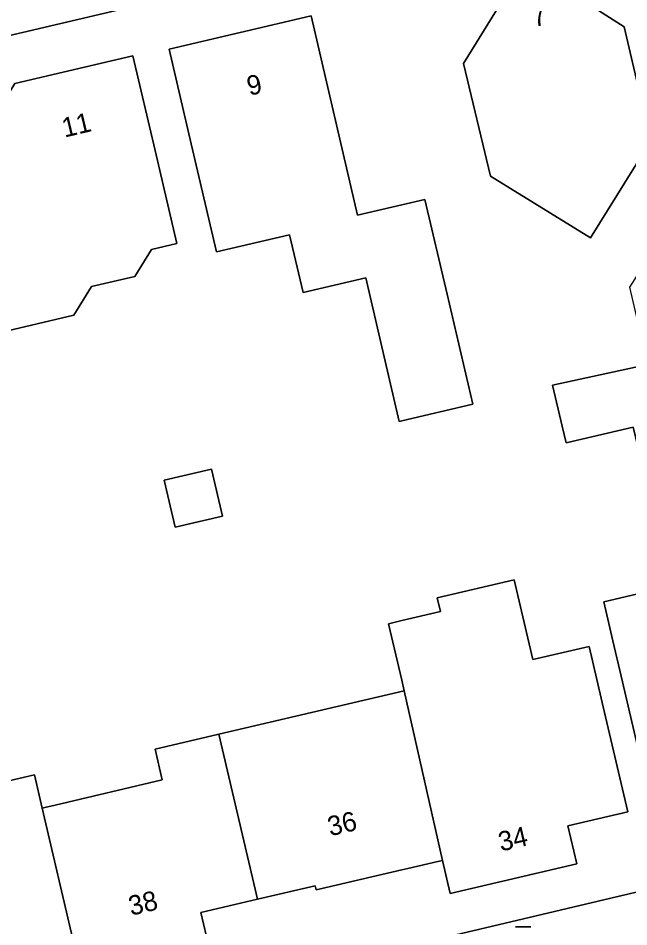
# Model space of a CAD drawing. Extents: x 158031 to 159244, y 380104 to 381214.
# Drawn here: x 158480.31 to 158511.66, y 380624.23 to 380670.9 of the extents above; entities that cross this region are included whole.
import ezdxf

# ---------------------------------------------------------------- set-up
doc = ezdxf.new("R2010")
doc.units = 0
for name, color, linetype in [('IMGEO_Erf', 7, 'Continuous'), ('IMGEO_Lichtmast', 7, 'Continuous'), ('IMGEO_Pand', 7, 'Continuous'), ('IMGEO_Pand_nummerreeks', 7, 'Continuous'), ('IMGEO_Voetpad_open', 7, 'Continuous')]:
    doc.layers.add(name, color=color, linetype=linetype)

msp = doc.modelspace()

# ---------------------------------------------------------------- linework, layer by layer
at = {"layer": 'IMGEO_Erf'}
for points in [[(158526.735, 380681.036), (158440.512, 380660.757), (158440.604, 380660.368), (158425.659, 380656.851), (158426.088, 380655.101), (158440.982, 380658.644), (158442.407, 380652.573), (158443.97, 380652.93), (158444.925, 380648.956), (158421.153, 380643.314), (158420.386, 380646.452), (158423.834, 380652.004), (158425.7, 380655.009), (158425.174, 380657.148), (158423.526, 380656.735)], [(158416.927, 380647.515), (158417.504, 380641.99), (158418.723, 380630.324), (158421.355, 380604.556), (158438.087, 380608.511), (158441.26, 380609.261), (158446.214, 380610.431), (158513.92, 380626.456), (158514.182, 380625.412), (158521.646, 380627.199), (158530.026, 380629.187), (158531.071, 380629.424), (158528.987, 380638.268), (158523.271, 380636.922), (158522.125, 380641.789), (158521.882, 380642.821), (158531.246, 380645.027), (158530.288, 380649.096), (158532.217, 380649.55), (158530.844, 380655.379)], [(158471.711, 380629.82), (158481.149, 380632.043), (158481.55, 380630.323), (158481.676, 380630.353), (158482.212, 380630.479), (158487.709, 380631.775), (158487.337, 380633.36), (158490.618, 380634.129), (158500.128, 380636.359), (158500, 380636.906), (158499.323, 380639.797), (158500, 380639.956), (158501.99, 380640.422), (158501.825, 380641.122), (158505.768, 380642.046), (158506.726, 380637.955), (158509.617, 380638.634), (158510.467, 380635.01), (158511.608, 380630.142), (158508.537, 380629.422), (158508.995, 380627.467), (158502.483, 380625.94), (158502.098, 380627.643), (158501.859, 380627.587), (158500.31, 380627.224), (158500, 380627.151), (158495.615, 380626.122), (158495.564, 380626.341), (158492.594, 380625.648), (158489.693, 380624.971), (158490.121, 380623.153)]]:
    msp.add_lwpolyline(points, dxfattribs=at)
for points in [[(158503.179, 380668.573), (158506.346, 380673.706), (158511.418, 380670.444), (158512.789, 380664.596), (158509.692, 380659.611), (158504.565, 380662.782)], [(158498.156, 380657.558), (158494.937, 380656.807), (158494.246, 380659.768), (158490.495, 380658.892), (158489.2, 380664.444), (158488.064, 380669.313), (158495.347, 380671.012), (158497.735, 380660.777), (158500, 380661.306), (158501.196, 380661.585), (158502.332, 380656.716), (158503.649, 380651.073), (158500, 380650.219), (158499.875, 380650.189)], [(158473.343, 380653.334), (158471.927, 380654.21), (158469.562, 380653.653), (158468.173, 380654.513), (158466.872, 380654.207), (158465.768, 380658.899), (158464.622, 380663.765), (158470.521, 380665.154), (158472.028, 380664.222), (158472.277, 380663.166), (158473.589, 380662.261), (158476.135, 380662.86), (158478.682, 380663.46), (158479.462, 380664.722), (158479.171, 380665.96), (158480.148, 380667.54), (158486.194, 380668.963), (158487.339, 380664.096), (158488.462, 380659.326), (158487.148, 380659.017), (158486.294, 380657.636), (158484.078, 380657.115), (158483.17, 380655.648), (158478.152, 380654.466)], [(158507.75, 380652.048), (158512.639, 380653.118), (158511.712, 380657.077), (158513.677, 380660.162), (158515.187, 380653.714), (158515.661, 380651.688), (158517.589, 380643.452), (158520.066, 380644.032), (158520.988, 380640.095), (158518.511, 380639.515), (158520.419, 380631.368), (158518.198, 380630.848), (158516.816, 380630.524), (158517.089, 380629.355), (158513.291, 380628.465), (158511.268, 380637.103), (158510.842, 380638.922), (158510.374, 380640.922), (158513.802, 380641.725), (158512.355, 380647.904), (158511.89, 380649.889), (158508.444, 380649.082), (158508.241, 380649.95)], [(158490.23, 380647.743), (158490.797, 380645.321), (158488.375, 380644.754), (158487.808, 380647.176)]]:
    msp.add_lwpolyline(points, close=True, dxfattribs=at)
at = {"layer": 'IMGEO_Lichtmast'}
for p, q in [((158505.845, 380624.231), (158506.635, 380624.231)), ((158506.635, 380624.231), (158505.845, 380624.231))]:
    msp.add_line(p, q, dxfattribs=at)
at = {"layer": 'IMGEO_Pand'}
for points in [[(158512.789, 380664.596), (158511.418, 380670.444), (158506.346, 380673.706), (158503.179, 380668.573), (158504.565, 380662.782), (158509.692, 380659.611)], [(158502.332, 380656.716), (158501.196, 380661.585), (158500, 380661.306), (158497.735, 380660.777), (158495.347, 380671.012), (158488.064, 380669.313), (158489.2, 380664.444), (158490.495, 380658.892), (158494.246, 380659.768), (158494.937, 380656.807), (158498.156, 380657.558), (158499.875, 380650.189), (158500, 380650.219), (158503.649, 380651.073)], [(158478.152, 380654.466), (158483.17, 380655.648), (158484.078, 380657.115), (158486.294, 380657.636), (158487.148, 380659.017), (158488.462, 380659.326), (158487.339, 380664.096), (158486.194, 380668.963), (158480.148, 380667.54), (158479.171, 380665.96), (158479.462, 380664.722), (158478.682, 380663.46), (158476.135, 380662.86)], [(158515.187, 380653.714), (158512.639, 380653.118), (158507.75, 380652.048), (158508.241, 380649.95), (158508.444, 380649.082), (158511.89, 380649.889), (158512.355, 380647.904), (158513.802, 380641.725), (158510.374, 380640.922), (158510.842, 380638.922), (158511.268, 380637.103), (158513.291, 380628.465), (158517.089, 380629.355), (158516.816, 380630.524), (158518.198, 380630.848), (158520.419, 380631.368), (158518.511, 380639.515), (158517.589, 380643.452), (158515.661, 380651.688)], [(158487.808, 380647.176), (158488.375, 380644.754), (158490.797, 380645.321), (158490.23, 380647.743)], [(158510.467, 380635.01), (158509.617, 380638.634), (158506.726, 380637.955), (158505.768, 380642.046), (158501.825, 380641.122), (158501.99, 380640.422), (158500, 380639.956), (158499.323, 380639.797), (158500, 380636.906), (158500.128, 380636.359), (158502.098, 380627.643), (158502.483, 380625.94), (158508.995, 380627.467), (158508.537, 380629.422), (158511.608, 380630.142)], [(158500.128, 380636.359), (158490.618, 380634.129), (158492.594, 380625.648), (158495.564, 380626.341), (158495.615, 380626.122), (158500, 380627.151), (158500.31, 380627.224), (158501.859, 380627.587), (158502.098, 380627.643)], [(158490.618, 380634.129), (158487.337, 380633.36), (158487.709, 380631.775), (158482.212, 380630.479), (158481.676, 380630.353), (158481.55, 380630.323), (158483.17, 380623.37), (158483.58, 380621.612), (158490.121, 380623.153), (158489.693, 380624.971), (158492.594, 380625.648)], [(158481.55, 380630.323), (158481.149, 380632.043), (158471.711, 380629.82), (158473.681, 380621.372), (158476.637, 380622.069), (158476.69, 380621.844), (158481.862, 380623.062), (158482.914, 380623.31), (158483.17, 380623.37)]]:
    msp.add_lwpolyline(points, close=True, dxfattribs=at)
at = {"layer": 'IMGEO_Voetpad_open'}
for points in [[(158423.526, 380656.735), (158425.174, 380657.148), (158440.512, 380660.757), (158526.735, 380681.036), (158540.619, 380684.345), (158545.869, 380685.589), (158566.205, 380690.407), (158570.101, 380691.331), (158573.471, 380692.129), (158646.034, 380709.321)], [(158560.659, 380635.948), (158557.728, 380635.248), (158552.455, 380633.99), (158541.542, 380631.386), (158538.841, 380631.254), (158531.071, 380629.424), (158530.026, 380629.187), (158521.646, 380627.199), (158514.182, 380625.412), (158513.92, 380626.456), (158446.214, 380610.431), (158441.26, 380609.261), (158438.087, 380608.511), (158421.355, 380604.556), (158421.491, 380603.098), (158507.663, 380623.484), (158508.189, 380621.442), (158511.199, 380622.155), (158513.36, 380622.667), (158513.405, 380622.477), (158516.204, 380623.141), (158516.005, 380623.969), (158540.301, 380629.746)]]:
    msp.add_lwpolyline(points, dxfattribs=at)

# ---------------------------------------------------------------- texts
at = {"layer": 'IMGEO_Pand_nummerreeks'}
for s, rotation, p in [('7', 13.3282, (158506.797, 380670.432)), ('9', 13.1313, (158492.182, 380666.906)), ('11', 13.3618, (158482.69, 380664.76)), ('36', 13.2067, (158496.328, 380628.878)), ('34', 13.1952, (158505.095, 380628.093)), ('38', 13.2525, (158486.106, 380624.796))]:
    msp.add_text(s, height=1, rotation=rotation, dxfattribs=at).set_placement(p)

doc.saveas('drawing.dxf')
